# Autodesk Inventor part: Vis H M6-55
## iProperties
Shininess: 64.0
Length Units: 11269
Angle Units: 11279
Time Units: 11290
Mass Units: 11283
Length Display Precision: 3
Angle Display Precision: 2
Compacted: True
Part Number: Vis H M6-55
Document SubType Name: Modeling
Created: 2006-01
Material: Par défaut
Designer: Fricot
Density: 0.0
Volumn: 0.0
Area: 0.0
PropertySet Name: Model Information
Control State: 0
Master: False
Checked Out: False
Author: Fricot
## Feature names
1. Base1
